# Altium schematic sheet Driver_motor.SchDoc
size A3
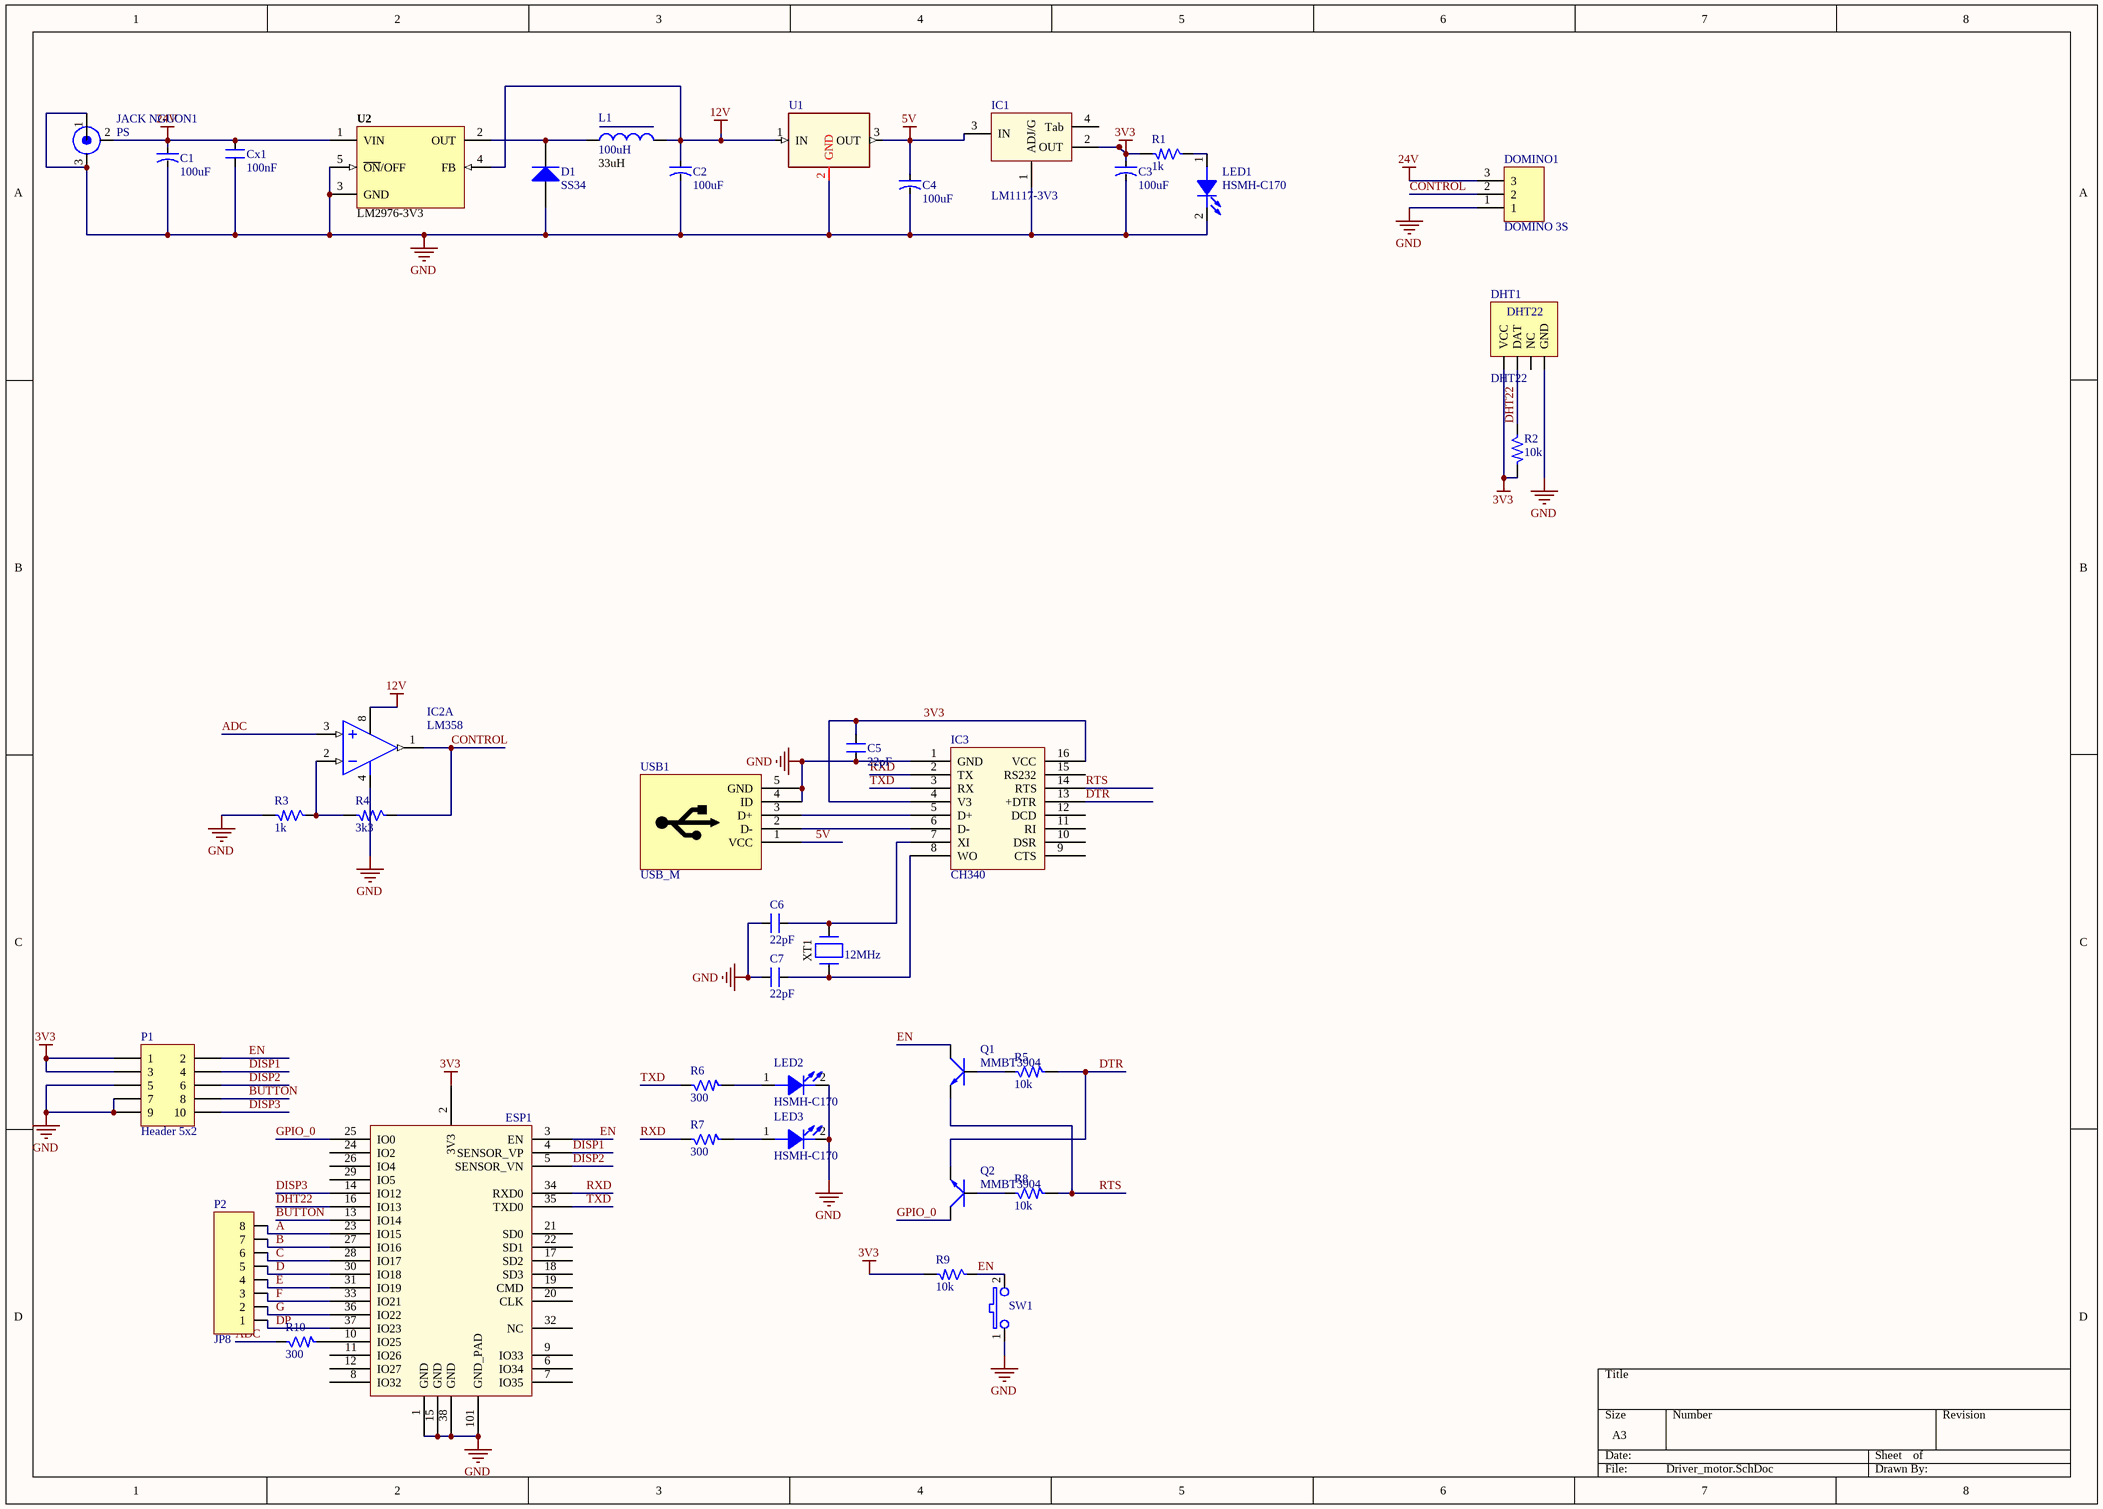
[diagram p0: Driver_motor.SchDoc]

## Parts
C1  100uF  [CAP-ALU-SMD-D]
C2  100uF  [CAP-ALU-SMD-D]
C3  100uF  [CAP-ALU-SMD-D]
C4  100uF  [CAP-ALU-SMD-D]
C5  22pF  [SM-CAP-0805]
C6  22pF  [SM-CAP-0805]
C7  22pF  [SM-CAP-0805]
Cx1  100nF  [CN-SMD-1206]
D1  SS34  [DIOT]
DHT1  DHT22  [DHT22]
DOMINO1  DOMINO 3S  [DOMINO 3S]
ESP1  ESP32S_Module  [ESP32]  (value not drawn)
IC1  LM1117-3V3  [LM1117-3V3-5V]
IC2  LM358  [SO8]  (part A of 2)
IC3  CH340  [ch340 g]
JACK_NGUON1  PS  [jack nguon]
L1  100uH  value 33uH  [cuon cam]
LED1  HSMH-C170  [LED]
LED2  HSMH-C170  [LED.SMD.GREEN]
LED3  HSMH-C170  [LED.SMD.GREEN]
P1  Header 5x2  [Header 5x2]
P2  JP8  [JP8-C1T]
Q1  MMBT3904  [MMBT 3904]
Q2  MMBT3904  [MMBT 3904]
R1  1k  [SM-RES-0805]
R2  10k  [SM-RES-0805]
R3  1k  [SM-RES-0805]
R4  3k3  [SM-RES-0805]
R5  10k  [SM-RES-0805]
R6  300  [SM-RES-0805]
R7  300  [SM-RES-0805]
R8  10k  [SM-RES-0805]
R9  10k  [SM-RES-0805]
R10  300  [SM-RES-0805]
SW1  PTS635  [BUTTON SMD 2PIN]  (value not drawn)
U1  LM78xx  [TO-263]  (value not drawn)
U2  LM2976-3V3  [TO263]
USB1  USB_M  [micro usb]
XT1  value 12MHz  [Crystal.HC49_N]  (hidden comment: Crystal2)

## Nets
3V3: C3.1 C5.2 DHT1.1(VCC) ESP1.2(3V3) IC1.2(OUT) IC3.4(V3) IC3.16(VCC) P1.1 P1.3 R1.2 R2.2 R9.2
5V: C4.1 IC1.3(IN) U1.3(OUT) USB1.1(VCC)
12V: C2.1 IC2.8(+V) L1.2 U1.1(IN) U2.4(FB)
24V: C1.1 Cx1.2 DOMINO1.3 JACK_NGUON1.2(SHIELD) U2.1(VIN)
GND: C1.2 C2.2 C3.2 C4.2 C5.1 C6.1 C7.1 Cx1.1 D1.1(A) DHT1.4(GND) DOMINO1.1 ESP1.1(GND) ESP1.15(GND) ESP1.38(GND) ESP1.101(GND_PAD) IC1.1(ADJ/G) IC2.4(-V) IC3.1(GND) JACK_NGUON1.1(CENTER) JACK_NGUON1.3(SHIELD) LED1.2(K) LED2.2(K) LED3.2(K) P1.5 P1.7 P1.9 R3.2 SW1.1 U1.2(GND) U2.3(GND) U2.5(~{ON}/OFF) USB1.4(ID) USB1.5(GND)
A: ESP1.23(IO15) P2.8
ADC: IC2.3(IN+) R10.1
B: ESP1.27(IO16) P2.7
BUTTON: ESP1.13(IO14) P1.8
C: ESP1.28(IO17) P2.6
CONTROL: DOMINO1.2 IC2.1(OUT) R4.1
D: ESP1.30(IO18) P2.5
DHT22: DHT1.2(DAT) ESP1.16(IO13) R2.1
DISP1: ESP1.4(SENSOR_VP) P1.4
DISP2: ESP1.5(SENSOR_VN) P1.6
DISP3: ESP1.14(IO12) P1.10
DP: ESP1.37(IO23) P2.1
DTR: IC3.13(+DTR) Q2.2(E) R5.2
E: ESP1.31(IO19) P2.4
EN: ESP1.3(EN) P1.2 Q1.3(C) R9.1 SW1.2
F: ESP1.33(IO21) P2.3
G: ESP1.36(IO22) P2.2
GPIO_0: ESP1.25(IO0) Q2.3(C)
RTS: IC3.14(RTS) Q1.2(E) R8.2
RXD: ESP1.34(RXD0) IC3.2(TX) R7.1
TXD: ESP1.35(TXD0) IC3.3(RX) R6.1
NetC6_2: C6.2 IC3.7(XI) XT1.2
NetC7_2: C7.2 IC3.8(WO) XT1.1
NetD1_2: D1.2(K) L1.1 U2.2(OUT)
NetESP1_10: ESP1.10(IO25) R10.2
NetIC2_2: IC2.2(IN-) R3.1 R4.2
NetIC3_5: IC3.5(D+) USB1.3(D+)
NetIC3_6: IC3.6(D-) USB1.2(D-)
NetLED1_1: LED1.1(A) R1.1
NetLED2_1: LED2.1(A) R6.2
NetLED3_1: LED3.1(A) R7.2
NetQ1_1: Q1.1(B) R5.1
NetQ2_1: Q2.1(B) R8.1

Not connected (* = marked no-connect by the designer): DHT1 3(NC); ESP1 6(IO34) 7(IO35) 8(IO32) 9(IO33) 11(IO26) 12(IO27) 17(SD2) 18(SD3) 19(CMD) 20(CLK) 21(SD0) 22(SD1) 24(IO2) 26(IO4) 29(IO5) 32(NC); IC1 4(Tab); IC3 9(CTS) 10(DSR) 11(RI) 12(DCD) 15(RS232)

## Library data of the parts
C1-C4 = CN-ALU-SMD: Polarized Capacitor (Axial)
C5-C7 = CN: 0,1uF/300V; Designed by: VanDungEvn
Cx1 = CN: Value: 33pF
D1 = Diode 1N4007: 1 Amp General Purpose Rectifier
DHT1 = DHT22: Manufacturer: W¨¹rth Elektronik eiSos GmbH; partNo: 613004143121; ComponentLink1 Description: Manufacturer; ComponentLink2 Description: Datasheet; NoPins: 04
ESP1 = ESP32S_Module: Esp-32S
IC1 = LM1117: 3v3; Value: LM317
IC2 = LM358: Low-Power Dual Operational Amplifier
JACK_NGUON1 = JACK_DC: DC Power Jack, 2.5mm, KLD Series, PCB Mount; Vendor: Nhat Tao
L1 = Inductor Ferrite: Cuon Cam L; Code_IEC: 1005; Vendor: Digikey
LED1-LED3 = LED_1: Typical GaAs SMD LED; Manufacturer: Lite-On Inc; Color: RED; Type: Cong ty RP; Vendor: Digikey
P1 = Header 5x2: Header, 10-Pin, 2-Row
P2 = JP8: WR-PHD 2.54 mm Angled Socket Header; Manufacturer: W¨¹rth Elektronik eiSos GmbH; partNo: 613008143121; ComponentLink1 Description: Manufacturer; ComponentLink2 Description: Datasheet; NoPins: 08
R1-R10 = R_1: Resistor 1/4W; Value: R1/4W - 1K
SW1 = BUTTON SMD 2PIN: Manufacturer: C&K Components; Manufacturer P/N: PTS635SL25SMTR LFS; Vendor: Digikey; Vendor P/N: CKN9119CT-ND
U1 = LM78xx: Regulator; Manufacturer: Fairchild Semiconductor Corporation; PSpiceTemplate: X^@REFDES %IN %OUT %GND @MODEL; Vendor: Digikey; Output Current: Up to 1A; V out: 5V; Tolerance: 4 %; Value: LM7805CT
U2 = LM2596: Max Input Voltage: 12 V; Max Output Current: 3 (6.0 peak) A; Max Output Voltage: mV
XT1 = Crystal2: Quarz Crystal; Vendor: Digikey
